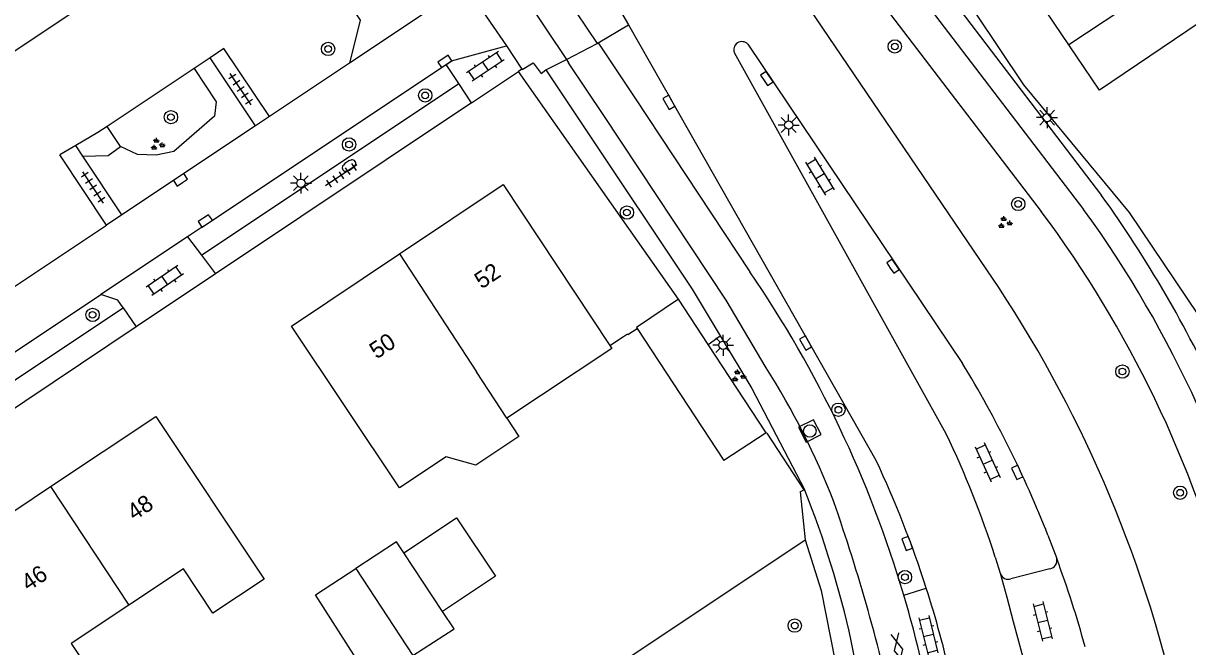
# Model space of a CAD drawing. Extents: x 137999 to 141000, y 397500 to 400501.
# Drawn here: x 138413.7 to 138483.4, y 399575 to 399612.3 of the extents above; entities that cross this region are included whole.
import ezdxf

# ---------------------------------------------------------------- set-up
doc = ezdxf.new("R2010")
doc.units = 0
for name, color, linetype in [('gg-afsc-erfafscheiding', 7, 'Continuous'), ('gg-afsc-hekwerk', 7, 'Continuous'), ('gg-afsc-muur', 7, 'Continuous'), ('gg-anno-huisnummerreeks BGT', 7, 'Continuous'), ('gg-bbg-bijgebouw', 7, 'Continuous'), ('gg-bbg-gedigitaliseerde bebouwing', 7, 'Continuous'), ('gg-bbg-gedigitaliseerde bijgebouw', 7, 'Continuous'), ('gg-bbg-hoofdgebouw', 7, 'Continuous'), ('gg-bbg-luifel en loopbrug', 7, 'Continuous'), ('gg-bbg-tussenscheiding', 7, 'Continuous'), ('gg-knt-verharding', 7, 'Continuous'), ('gg-knt-verharding nz', 7, 'Continuous'), ('gt-grn-groengrens', 7, 'Continuous'), ('gt-grn-vlakafsluiter', 7, 'Continuous'), ('gt-grn-weggrens', 7, 'Continuous'), ('gt-symb-boom', 7, 'Continuous'), ('gt-symb-brandkraan', 7, 'Continuous'), ('gt-symb-gesloten verharding', 7, 'Continuous'), ('gt-symb-groenvak', 7, 'Continuous'), ('gt-symb-klinker verharding', 7, 'Continuous'), ('gt-symb-kolk', 7, 'Continuous'), ('gt-symb-lichtmast', 7, 'Continuous'), ('gt-symb-rioolschacht', 7, 'Continuous'), ('gt-symb-tegel verharding', 7, 'Continuous')]:
    doc.layers.add(name, color=color, linetype=linetype)

# ---------------------------------------------------------------- blocks, each defined once
blk = doc.blocks.new('gt0-KOLK')
at = {"layer": 'gt-symb-kolk'}
blk.add_lwpolyline([(0, 0), (0.375, 0), (0.375, 0.4), (-0.375, 0.4), (-0.375, 0), (0, 0)], dxfattribs=at)
blk = doc.blocks.new('gt0-LMAST')
at = {"layer": 'gt-symb-lichtmast'}
for p, q in [((-0.182, 0.173), (-0.447, 0.438)), ((-0.005, 0.246), (-0.005, 0.621)), ((0.172, 0.173), (0.437, 0.438)), ((-0.255, -0.004), (-0.63, -0.004)), ((-0.182, -0.181), (-0.447, -0.446)), ((-0.005, -0.254), (-0.005, -0.629)), ((0.437, -0.446), (0.172, -0.181)), ((0.245, -0.004), (0.62, -0.004))]:
    blk.add_line(p, q, dxfattribs=at)
blk.add_circle((-0.005, -0.004), 0.25, dxfattribs=at)
blk = doc.blocks.new('gt0-BOOM')
at = {"layer": 'gt-symb-boom'}
for radius in [0.4, 0.2]:
    blk.add_circle((0, 0), radius, dxfattribs=at)
blk = doc.blocks.new('gt0-GRVAK')
at = {"layer": 'gt-symb-groenvak'}
for p, q in [((-0.11, 0.189), (-0.228, 0.24)), ((-0.182, 0.153), (0.088, 0.153)), ((-0.091, 0.211), (-0.156, 0.322)), ((-0.047, 0.214), (-0.047, 0.393)), ((-0.004, 0.211), (0.061, 0.322)), ((0.015, 0.189), (0.133, 0.24)), ((0.262, -0.052), (0.197, 0.059)), ((0.305, -0.049), (0.305, 0.13)), ((0.349, -0.052), (0.414, 0.059)), ((-0.245, -0.228), (-0.363, -0.177)), ((-0.318, -0.264), (-0.047, -0.264)), ((-0.226, -0.206), (-0.291, -0.095)), ((-0.183, -0.203), (-0.183, -0.024)), ((-0.139, -0.206), (-0.074, -0.095)), ((-0.12, -0.228), (-0.002, -0.177)), ((0.243, -0.074), (0.125, -0.023)), ((0.17, -0.11), (0.441, -0.11)), ((0.368, -0.074), (0.486, -0.023))]:
    blk.add_line(p, q, dxfattribs=at)
blk = doc.blocks.new('gt0-KL1')
at = {"layer": 'gt-symb-klinker verharding'}
for p, q in [((-1.15, 0.3), (1.15, 0.3)), ((-1, -0.3), (-1, 0.3)), ((-0.5, 0.3), (-0.5, 0.45)), ((0, -0.3), (0, 0.3)), ((0.5, 0.3), (0.5, 0.45)), ((1, -0.3), (1, 0.3)), ((-1.15, -0.3), (1.15, -0.3)), ((-0.5, -0.45), (-0.5, -0.3)), ((0.5, -0.45), (0.5, -0.3))]:
    blk.add_line(p, q, dxfattribs=at)
blk = doc.blocks.new('gt0-RS')
at = {"layer": 'gt-symb-rioolschacht'}
blk.add_lwpolyline([(-0.5, -0.5), (0.5, -0.5), (0.5, 0.5), (-0.5, 0.5)], close=True, dxfattribs=at)
blk.add_circle((0, 0), 0.375, dxfattribs=at)
blk = doc.blocks.new('gt0-GESVH1')
at = {"layer": 'gt-symb-gesloten verharding'}
for p, q in [((-0.992, -0.261), (0.008, 0.239)), ((0.008, -0.261), (-0.992, 0.239)), ((0.008, 0.239), (1.008, -0.261)), ((1.008, 0.239), (0.008, -0.261))]:
    blk.add_line(p, q, dxfattribs=at)
blk = doc.blocks.new('gt0-TEG1')
at = {"layer": 'gt-symb-tegel verharding'}
for p, q in [((-1.125, 0), (1.125, 0)), ((-0.9, -0.25), (-0.9, 0.25)), ((-0.45, -0.25), (-0.45, 0.25)), ((0, -0.25), (0, 0.25)), ((0.45, -0.25), (0.45, 0.25)), ((0.9, -0.25), (0.9, 0.25))]:
    blk.add_line(p, q, dxfattribs=at)
blk = doc.blocks.new('gt0-BR')
at = {"layer": 'gt-symb-brandkraan'}
for centre, radius, start, end in [((-0.244, 0), 0.206, 107.56694, 252.43307), ((0.599, -2.664), 3, 106.89205, 107.56694), ((0, -0.691), 0.938, 73.10799, 106.89205), ((-0.599, -2.664), 3, 72.43309, 73.10799), ((0.244, 0), 0.206, 287.56695, 72.43309), ((0.599, 2.664), 3, 252.43307, 253.10797), ((0, 0.691), 0.938, 253.10797, 286.89206), ((-0.599, 2.664), 3, 286.89206, 287.56695)]:
    blk.add_arc(centre, radius, start, end, dxfattribs=at)

msp = doc.modelspace()

# ---------------------------------------------------------------- linework, layer by layer
at = {"layer": 'gg-afsc-erfafscheiding'}
for p, q in [((138425.721, 399610.821), (138424.89, 399610.267)), ((138424.89, 399610.267), (138423.93, 399609.628)), ((138423.93, 399609.628), (138418.727, 399606.16)), ((138416.851, 399605.018), (138415.9, 399604.462)), ((138454.694, 399593.116), (138455.417, 399593.629)), ((138448.81, 399593.051), (138449.628, 399593.586)), ((138460.46, 399584.44), (138460.425, 399584.416))]:
    msp.add_line(p, q, dxfattribs=at)
for points in [[(138462.152, 399625.696), (138473.561, 399608.651), (138479.895, 399601.002), (138486.747, 399590.824)], [(138418.727, 399606.16), (138418.182, 399605.797), (138416.851, 399605.018)], [(138460.494, 399581.419), (138461.456, 399578.392), (138463.398, 399568.575)]]:
    msp.add_lwpolyline(points, dxfattribs=at)
at = {"layer": 'gg-afsc-hekwerk'}
msp.add_line((138460.209, 399584.291), (138460.494, 399581.419), dxfattribs=at)
at = {"layer": 'gg-afsc-muur'}
for p, q in [((138458.206, 399587.8), (138460.417, 399584.428)), ((138460.209, 399584.291), (138460.417, 399584.428)), ((138460.417, 399584.428), (138460.425, 399584.416))]:
    msp.add_line(p, q, dxfattribs=at)
msp.add_lwpolyline([(138449.628, 399593.586), (138449.874, 399593.755), (138449.897, 399593.718), (138450.447, 399594.062)], dxfattribs=at)
at = {"layer": 'gg-bbg-bijgebouw'}
for p, q in [((138476.293, 399611.038), (138474.49, 399613.7)), ((138478.12, 399608.341), (138476.293, 399611.038)), ((138454.694, 399593.116), (138452.919, 399595.82)), ((138450.447, 399594.062), (138455.63, 399586.17)), ((138458.17, 399587.82), (138454.694, 399593.116)), ((138458.17, 399587.82), (138455.63, 399586.17))]:
    msp.add_line(p, q, dxfattribs=at)
msp.add_lwpolyline([(138452.919, 399595.82), (138450.406, 399594.125), (138450.447, 399594.062)], dxfattribs=at)
at = {"layer": 'gg-bbg-gedigitaliseerde bebouwing'}
msp.add_line((138448.93, 399592.87), (138442.648, 399588.702), dxfattribs=at)
for points in [[(138439.01, 399586.402), (138436.219, 399584.539), (138429.76, 399594.22)], [(138421.64, 399588.8), (138428.119, 399579.071), (138425.057, 399577.034), (138423.291, 399579.688), (138420.024, 399577.515)], [(138442.648, 399588.702), (138443.376, 399587.605), (138440.791, 399585.889), (138439.01, 399586.402)], [(138420.024, 399577.515), (138416.581, 399575.224), (138418.358, 399572.553), (138415.448, 399570.618), (138408.97, 399580.37)]]:
    msp.add_lwpolyline(points, dxfattribs=at)
at = {"layer": 'gg-bbg-gedigitaliseerde bijgebouw'}
msp.add_line((138438.802, 399577.148), (138436.479, 399580.648), dxfattribs=at)
for points in [[(138482.642, 399615.272), (138484.572, 399616.559), (138486.364, 399613.914), (138478.12, 399608.341)], [(138436.479, 399580.648), (138436.045, 399581.302), (138433.619, 399579.718)], [(138437.025, 399574.502), (138434.56, 399572.892), (138431.193, 399578.134), (138433.619, 399579.718)], [(138437.025, 399574.502), (138439.49, 399576.111), (138438.802, 399577.148)]]:
    msp.add_lwpolyline(points, dxfattribs=at)
at = {"layer": 'gg-bbg-hoofdgebouw'}
for p, q in [((138417.226, 399613.354), (138411.45, 399609.51)), ((138429.76, 399594.22), (138436.22, 399598.53)), ((138448.81, 399593.051), (138448.93, 399592.87)), ((138415.346, 399584.612), (138421.64, 399588.8)), ((138408.97, 399580.37), (138415.346, 399584.612))]:
    msp.add_line(p, q, dxfattribs=at)
msp.add_lwpolyline([(138436.22, 399598.53), (138442.44, 399602.68), (138448.81, 399593.051)], dxfattribs=at)
at = {"layer": 'gg-bbg-luifel en loopbrug'}
msp.add_lwpolyline([(138436.479, 399580.648), (138439.645, 399582.749), (138441.968, 399579.25), (138438.802, 399577.148)], dxfattribs=at)
at = {"layer": 'gg-bbg-tussenscheiding'}
for p, q in [((138482.642, 399615.272), (138476.293, 399611.038)), ((138436.22, 399598.53), (138440.833, 399591.476)), ((138442.648, 399588.702), (138440.833, 399591.476)), ((138415.346, 399584.612), (138420.024, 399577.515)), ((138433.619, 399579.718), (138437.025, 399574.502))]:
    msp.add_line(p, q, dxfattribs=at)
at = {"layer": 'gg-knt-verharding'}
for p, q in [((138441.943, 399620.182), (138448.061, 399611.124)), ((138466.574, 399617.313), (138478.243, 399602.036)), ((138465.377, 399616.616), (138477.17, 399601.2)), ((138448.072, 399615.474), (138449.928, 399612.235)), ((138463.552, 399615.554), (138474.63, 399601.08)), ((138440.177, 399614.565), (138442.627, 399610.99)), ((138472.096, 399596.52), (138460.416, 399613.729)), ((138437.995, 399613.112), (138433.228, 399609.937)), ((138448.123, 399611.161), (138449.928, 399612.235)), ((138449.928, 399612.235), (138451.908, 399608.779)), ((138448.061, 399611.124), (138448.123, 399611.161)), ((138448.123, 399611.161), (138450.305, 399607.867)), ((138457.069, 399611.08), (138469.92, 399591.98)), ((138428.436, 399606.746), (138425.721, 399610.821)), ((138442.627, 399610.99), (138443.554, 399609.592)), ((138468.941, 399587.768), (138456.27, 399610.56)), ((138424.383, 399600.121), (138439.011, 399609.861)), ((138427.604, 399606.192), (138424.89, 399610.267)), ((138433.228, 399609.937), (138428.436, 399606.746)), ((138439.769, 399608.725), (138439.011, 399609.861)), ((138446.215, 399610.172), (138446.35, 399609.971)), ((138448.448, 399606.812), (138446.35, 399609.971)), ((138440.536, 399607.575), (138443.342, 399609.45)), ((138443.554, 399609.592), (138443.342, 399609.45)), ((138444.712, 399609.332), (138444.99, 399609.54)), ((138444.99, 399609.54), (138447.26, 399606.136)), ((138424.374, 399598.463), (138439.769, 399608.725)), ((138440.536, 399607.575), (138439.769, 399608.725)), ((138451.908, 399608.779), (138452.525, 399607.702)), ((138440.536, 399607.575), (138425.216, 399597.339)), ((138450.305, 399607.867), (138457.2, 399597.46)), ((138464.751, 399586.178), (138452.525, 399607.702)), ((138427.604, 399606.192), (138419.614, 399600.87)), ((138428.436, 399606.746), (138427.604, 399606.192)), ((138417.281, 399604.373), (138416.851, 399605.018)), ((138418.698, 399600.261), (138415.9, 399604.462)), ((138419.614, 399600.87), (138417.281, 399604.373)), ((138419.614, 399600.87), (138418.698, 399600.261)), ((138411.383, 399595.389), (138418.698, 399600.261)), ((138423.548, 399599.565), (138424.374, 399598.463)), ((138424.374, 399598.463), (138425.216, 399597.339)), ((138425.216, 399597.339), (138420.463, 399594.163)), ((138403.046, 399585.914), (138418.343, 399596.099)), ((138403.842, 399584.766), (138419.679, 399595.312)), ((138419.679, 399595.312), (138420.463, 399594.163)), ((138420.463, 399594.163), (138404.653, 399583.599)), ((138475.032, 399581.708), (138475.557, 399580.32)), ((138472.188, 399579.413), (138471.885, 399580.38)), ((138475.156, 399579.7), (138472.821, 399579.087)), ((138466.409, 399578.112), (138467.75, 399578.542))]:
    msp.add_line(p, q, dxfattribs=at)
for points in [[(138440.315, 399619.017), (138441.23, 399617.62), (138446.215, 399610.172)], [(138432.155, 399615.109), (138433.865, 399612.517), (138433.228, 399609.937)], [(138439.011, 399609.861), (138439.34, 399610.08), (138442.627, 399610.99)], [(138443.554, 399609.592), (138443.574, 399609.562), (138444.227, 399609.974), (138444.712, 399609.332)], [(138458.17, 399591.72), (138455.78, 399595.77), (138448.448, 399606.812)], [(138447.26, 399606.136), (138453.74, 399596.42), (138455.417, 399593.629)], [(138419.679, 399595.312), (138419.364, 399595.771), (138418.343, 399596.099)], [(138455.417, 399593.629), (138457.31, 399590.48), (138460.46, 399584.44)], [(138473.745, 399573.647), (138472.97, 399576.52), (138472.599, 399577.973), (138472.188, 399579.413)], [(138464.182, 399569.982), (138463.81, 399572.582), (138463.261, 399575.392)]]:
    msp.add_lwpolyline(points, dxfattribs=at)
for centre, radius, start, end in [((138456.713, 399610.752), 0.483, 123.04167, 203.40142), ((138456.714, 399610.752), 0.483, 42.73358, 123.08474), ((138419.518, 399559.801), 72.335, 24.63082, 35.72396), ((138420.046, 399560.332), 68.116, 14.6464, 36.74246), ((138422.409, 399561.525), 67.623, 12.88505, 35.9235), ((138400.361, 399558.541), 68.887, 16.50539, 34.40038), ((138407.991, 399554.418), 76.695, 12.1369, 33.29533), ((138419.273, 399567.045), 46.064, 21.19664, 32.38977), ((138412.362, 399556.927), 67.392, 21.57451, 31.34121), ((138417.602, 399563.03), 56.988, 17.72529, 25.7277), ((138406.538, 399558.908), 64.284, 17.78368, 25.10065), ((138407.106, 399562.965), 57.514, 12.47781, 21.92423), ((138353.511, 399545.888), 115.097, 12.40068, 19.17898), ((138475.075, 399580.192), 0.499, 279.39816, 14.81435), ((138415.805, 399558.167), 63.726, 15.34684, 20.34215), ((138472.668, 399579.568), 0.505, 197.88501, 287.61734), ((138406.665, 399558.922), 64.158, 12.65854, 17.80635), ((138400.142, 399558.481), 69.114, 11.83265, 16.50146)]:
    msp.add_arc(centre, radius, start, end, dxfattribs=at)
at = {"layer": 'gg-knt-verharding nz'}
for p, q in [((138424.383, 399600.121), (138423.548, 399599.565)), ((138423.548, 399599.565), (138418.343, 399596.099))]:
    msp.add_line(p, q, dxfattribs=at)
at = {"layer": 'gt-grn-groengrens'}
for p, q in [((138452.919, 399595.82), (138443.342, 399609.45)), ((138419.532, 399604.953), (138418.727, 399606.16))]:
    msp.add_line(p, q, dxfattribs=at)
for points in [[(138423.93, 399609.628), (138425.257, 399607.636), (138425.159, 399606.771), (138422.729, 399604.656), (138421.664, 399604.437), (138420.538, 399604.473), (138419.532, 399604.953)], [(138417.281, 399604.373), (138418.792, 399604.417), (138419.532, 399604.953)]]:
    msp.add_lwpolyline(points, dxfattribs=at)
at = {"layer": 'gt-grn-vlakafsluiter'}
for p, q in [((138458.206, 399587.8), (138458.17, 399587.82)), ((138433.113, 399563.182), (138460.494, 399581.419))]:
    msp.add_line(p, q, dxfattribs=at)
at = {"layer": 'gt-grn-weggrens'}
for p, q in [((138446.215, 399610.172), (138448.061, 399611.124)), ((138444.99, 399609.54), (138446.215, 399610.172))]:
    msp.add_line(p, q, dxfattribs=at)

# ---------------------------------------------------------------- block references
at = {"layer": 'gt-symb-boom'}
for p in [(138431.955, 399610.797), (138465.867, 399610.948), (138437.767, 399608.019), (138422.548, 399606.716), (138433.205, 399605.084), (138449.839, 399601.009), (138473.252, 399601.523), (138417.86, 399594.885), (138479.487, 399591.496), (138462.49, 399589.213), (138482.946, 399584.247), (138466.477, 399579.196), (138459.879, 399576.295)]:
    msp.add_blockref('gt0-BOOM', p, dxfattribs=at)
at = {"layer": 'gt-symb-brandkraan', "rotation": -146.21457204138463}
msp.add_blockref('gt0-BR', (138433.208, 399603.821), dxfattribs=at)
at = {"layer": 'gt-symb-gesloten verharding', "rotation": -77.0611893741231}
msp.add_blockref('gt0-GESVH1', (138466.1, 399574.849), dxfattribs=at)
at = {"layer": 'gt-symb-groenvak'}
for p in [(138421.725, 399605.078), (138472.439, 399600.394), (138456.499, 399591.223)]:
    msp.add_blockref('gt0-GRVAK', p, dxfattribs=at)
at = {"layer": 'gt-symb-klinker verharding'}
for p, rotation in [((138441.36, 399609.758), -146.00796028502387), ((138461.382, 399603.191), -58.82018224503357), ((138422.177, 399596.939), -145.7217334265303), ((138471.424, 399586.074), -65.22886109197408), ((138474.716, 399576.546), -76.11658196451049), ((138467.882, 399575.718), -76.11658196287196)]:
    msp.add_blockref('gt0-KL1', p, dxfattribs=dict(at, rotation=rotation))
at = {"layer": 'gt-symb-kolk'}
for p, rotation in [((138439.05, 399609.888), 33.658271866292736), ((138458.043, 399608.915), -56.08748741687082), ((138452.525, 399607.702), 119.7946172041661), ((138423.233, 399602.801), 33.658271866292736), ((138424.714, 399600.341), 33.65827186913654), ((138465.595, 399597.686), -56.29404346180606), ((138460.701, 399593.305), 119.74488129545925), ((138473.38, 399585.546), 114.89920052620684), ((138466.8, 399581.284), 110.3012499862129)]:
    msp.add_blockref('gt0-KOLK', p, dxfattribs=dict(at, rotation=rotation))
at = {"layer": 'gt-symb-lichtmast'}
for p in [(138459.52, 399606.249), (138474.986, 399606.69), (138430.332, 399602.768), (138455.601, 399593.074)]:
    msp.add_blockref('gt0-LMAST', p, dxfattribs=at)
at = {"layer": 'gt-symb-rioolschacht', "rotation": 27.00065470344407}
msp.add_blockref('gt0-RS', (138460.783, 399587.941), dxfattribs=at)
at = {"layer": 'gt-symb-tegel verharding'}
for p, rotation in [((138426.72, 399608.389), 123.65827186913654), ((138417.893, 399602.51), 123.65827186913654), ((138432.744, 399603.236), -146.500599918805)]:
    msp.add_blockref('gt0-TEG1', p, dxfattribs=dict(at, rotation=rotation))

# ---------------------------------------------------------------- texts
at = {"layer": 'gg-anno-huisnummerreeks BGT'}
for s, rotation, p in [('52', 33.7, (138441.139, 399596.402)), ('50', 33.7, (138434.855, 399592.21)), ('48', 33.6, (138420.353, 399582.54)), ('46', 33.6, (138414.018, 399578.324))]:
    msp.add_text(s, height=1, rotation=rotation, dxfattribs=at).set_placement(p)

doc.saveas('drawing.dxf')
